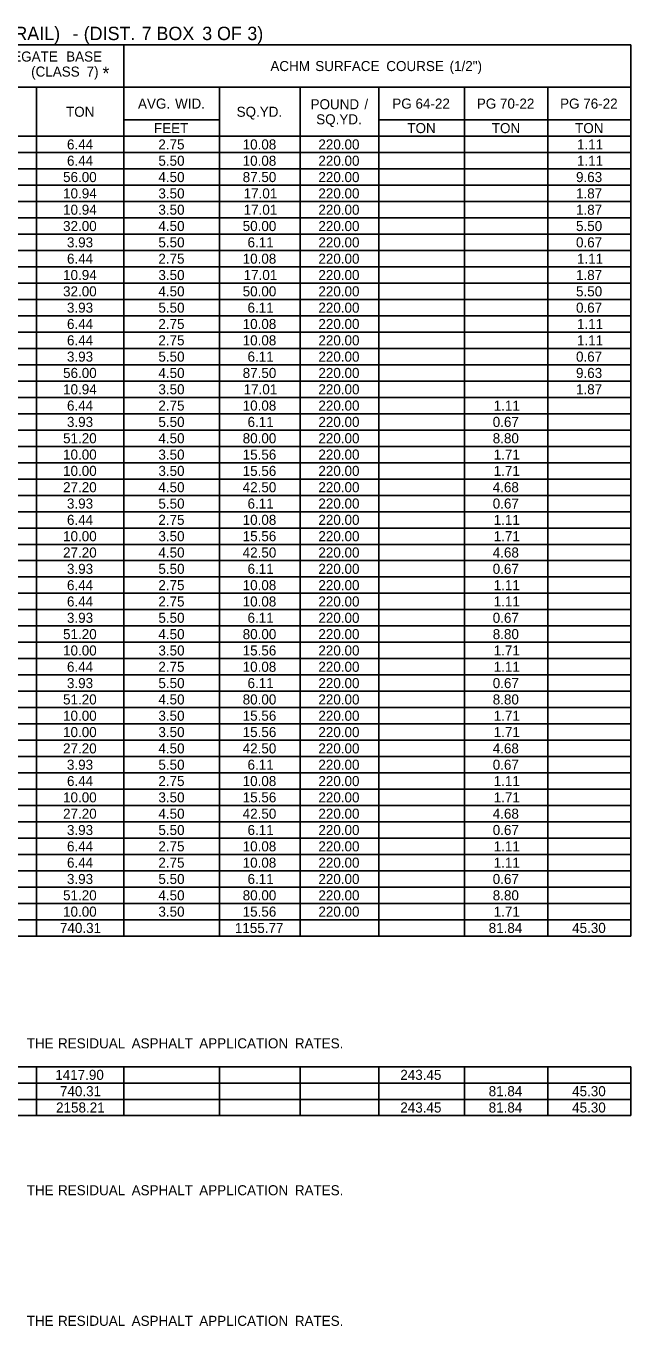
# Model space of a CAD drawing. Extents: x 544478 to 1930787, y -1948294 to 596640.
# Drawn here: x 554523 to 554884, y -1946915 to -1946138 of the extents above; entities that cross this region are included whole.
import ezdxf

# ---------------------------------------------------------------- set-up
doc = ezdxf.new("R2010")
doc.units = 0
doc.layers.add('Default', color=7, linetype='Continuous')

msp = doc.modelspace()

# ---------------------------------------------------------------- linework, layer by layer
at = {"layer": 'Default'}
for p, q in [((554061.9, -1946149.42), (554884.32, -1946149.42)), ((554581.58, -1946681.77), (554581.58, -1946149.42)), ((554884.32, -1946681.77), (554884.32, -1946149.42)), ((554479.69, -1946174.77), (554884.32, -1946174.77)), ((554529.42, -1946681.77), (554529.42, -1946174.77)), ((554638.62, -1946174.77), (554686.88, -1946174.77)), ((554638.62, -1946681.77), (554638.62, -1946174.77)), ((554686.88, -1946681.77), (554686.88, -1946174.77)), ((554733.68, -1946681.77), (554733.68, -1946174.77)), ((554784.87, -1946681.77), (554784.87, -1946174.77)), ((554834.59, -1946681.77), (554834.59, -1946174.77)), ((554581.58, -1946194.27), (554638.62, -1946194.27)), ((554581.58, -1946204.02), (554581.58, -1946194.27)), ((554638.62, -1946681.77), (554638.62, -1946194.27)), ((554733.68, -1946194.27), (554884.32, -1946194.27)), ((554061.9, -1946204.02), (554884.32, -1946204.02)), ((554479.69, -1946204.02), (554638.62, -1946204.02)), ((554529.42, -1946681.77), (554529.42, -1946204.02)), ((554638.62, -1946204.02), (554884.32, -1946204.02)), ((554686.88, -1946681.77), (554686.88, -1946204.02)), ((554307.6, -1946213.77), (554884.32, -1946213.77)), ((554307.6, -1946223.52), (554884.32, -1946223.52)), ((554307.6, -1946233.27), (554884.32, -1946233.27)), ((554307.6, -1946243.02), (554884.32, -1946243.02)), ((554307.6, -1946252.77), (554884.32, -1946252.77)), ((554307.6, -1946262.52), (554884.32, -1946262.52)), ((554307.6, -1946272.27), (554884.32, -1946272.27)), ((554307.6, -1946282.02), (554884.32, -1946282.02)), ((554307.6, -1946291.77), (554884.32, -1946291.77)), ((554307.6, -1946301.52), (554884.32, -1946301.52)), ((554307.6, -1946311.27), (554884.32, -1946311.27)), ((554307.6, -1946321.02), (554581.58, -1946321.02)), ((554529.42, -1946321.02), (554581.58, -1946321.02)), ((554581.58, -1946321.02), (554884.32, -1946321.02)), ((554307.6, -1946330.77), (554884.32, -1946330.77)), ((554307.6, -1946340.52), (554581.58, -1946340.52)), ((554529.42, -1946340.52), (554581.58, -1946340.52)), ((554581.58, -1946340.52), (554884.32, -1946340.52)), ((554307.6, -1946350.27), (554581.58, -1946350.27)), ((554529.42, -1946350.27), (554581.58, -1946350.27)), ((554581.58, -1946350.27), (554884.32, -1946350.27)), ((554061.9, -1946360.02), (554884.32, -1946360.02)), ((554307.6, -1946369.77), (554884.32, -1946369.77)), ((554307.6, -1946379.52), (554884.32, -1946379.52)), ((554307.6, -1946389.27), (554884.32, -1946389.27)), ((554307.6, -1946399.02), (554884.32, -1946399.02)), ((554307.6, -1946408.77), (554884.32, -1946408.77)), ((554307.6, -1946418.52), (554884.32, -1946418.52)), ((554307.6, -1946428.27), (554884.32, -1946428.27)), ((554307.6, -1946438.02), (554884.32, -1946438.02)), ((554307.6, -1946447.77), (554884.32, -1946447.77)), ((554307.6, -1946457.52), (554884.32, -1946457.52)), ((554307.6, -1946467.27), (554884.32, -1946467.27)), ((554307.6, -1946477.02), (554581.58, -1946477.02)), ((554529.42, -1946477.02), (554581.58, -1946477.02)), ((554581.58, -1946477.02), (554884.32, -1946477.02)), ((554307.6, -1946486.77), (554884.32, -1946486.77)), ((554307.6, -1946496.52), (554581.58, -1946496.52)), ((554529.42, -1946496.52), (554581.58, -1946496.52)), ((554581.58, -1946496.52), (554884.32, -1946496.52)), ((554307.6, -1946506.27), (554581.58, -1946506.27)), ((554529.42, -1946506.27), (554581.58, -1946506.27)), ((554581.58, -1946506.27), (554884.32, -1946506.27)), ((554061.9, -1946516.02), (554884.32, -1946516.02)), ((554307.6, -1946525.77), (554884.32, -1946525.77)), ((554307.6, -1946535.52), (554884.32, -1946535.52)), ((554307.6, -1946545.27), (554884.32, -1946545.27)), ((554307.6, -1946555.02), (554884.32, -1946555.02)), ((554307.6, -1946564.77), (554884.32, -1946564.77)), ((554307.6, -1946574.52), (554884.32, -1946574.52)), ((554307.6, -1946584.27), (554884.32, -1946584.27)), ((554307.6, -1946594.02), (554884.32, -1946594.02)), ((554307.6, -1946603.77), (554884.32, -1946603.77)), ((554307.6, -1946613.52), (554884.32, -1946613.52)), ((554307.6, -1946623.27), (554884.32, -1946623.27)), ((554307.6, -1946633.02), (554581.58, -1946633.02)), ((554529.42, -1946633.02), (554581.58, -1946633.02)), ((554581.58, -1946633.02), (554884.32, -1946633.02)), ((554307.6, -1946642.77), (554884.32, -1946642.77)), ((554307.6, -1946652.52), (554581.58, -1946652.52)), ((554529.42, -1946652.52), (554581.58, -1946652.52)), ((554581.58, -1946652.52), (554884.32, -1946652.52)), ((554307.6, -1946662.27), (554581.58, -1946662.27)), ((554529.42, -1946662.27), (554581.58, -1946662.27)), ((554581.58, -1946662.27), (554884.32, -1946662.27)), ((554061.9, -1946672.02), (554884.32, -1946672.02)), ((554733.68, -1946681.77), (554733.68, -1946672.02)), ((554307.6, -1946681.77), (554884.32, -1946681.77)), ((554244.23, -1946759.77), (554834.59, -1946759.77)), ((554244.23, -1946759.77), (554884.32, -1946759.77)), ((554529.42, -1946789.02), (554529.42, -1946759.77)), ((554581.58, -1946789.02), (554581.58, -1946759.77)), ((554638.62, -1946789.02), (554638.62, -1946759.77)), ((554686.88, -1946789.02), (554686.88, -1946759.77)), ((554733.68, -1946789.02), (554733.68, -1946759.77)), ((554784.87, -1946789.02), (554784.87, -1946759.77)), ((554834.59, -1946789.02), (554834.59, -1946759.77)), ((554884.32, -1946789.02), (554884.32, -1946759.77)), ((554244.23, -1946769.52), (554884.32, -1946769.52)), ((554244.23, -1946779.27), (554884.32, -1946779.27)), ((554581.58, -1946789.02), (554581.58, -1946779.27)), ((554638.62, -1946789.02), (554638.62, -1946779.27)), ((554686.88, -1946789.02), (554686.88, -1946779.27)), ((554733.68, -1946789.02), (554733.68, -1946779.27)), ((554244.23, -1946789.02), (554884.32, -1946789.02))]:
    msp.add_line(p, q, dxfattribs=at)

# ---------------------------------------------------------------- texts
for s, height, p in [(' GUARDRAIL)', 8, (554474.5, -1946146.6)), (' -', 8, (554547.81, -1946146.6)), (' (DIST.', 8, (554554.55, -1946146.6)), (' 7', 8, (554589.17, -1946146.6)), (' BOX', 8, (554598, -1946146.6)), (' 3', 8, (554625.31, -1946146.6)), (' OF', 8, (554634.15, -1946146.6)), (' 3)', 8, (554652.26, -1946146.6)), ('AGGREGATE', 6, (554491.22, -1946159.4)), (' BASE', 6, (554544.84, -1946159.4)), ('ACHM', 6, (554669.01, -1946165.1)), (' SURFACE', 6, (554693.56, -1946165.1)), (' COURSE', 6, (554736, -1946165.1)), (' (1/2")', 6, (554773.78, -1946165.1)), (' (CLASS', 6, (554523.91, -1946168.4)), (' 7)', 6, (554557.03, -1946168.4)), ('*', 8, (554568.7, -1946170.4)), ('AVG.', 6, (554589.95, -1946187.52)), (' WID.', 6, (554609.87, -1946187.52)), ('POUND', 6, (554693.01, -1946187.9)), (' /', 6, (554722.88, -1946187.9)), ('PG', 6, (554741.8, -1946187.52)), (' 64-22', 6, (554753.41, -1946187.52)), ('PG', 6, (554792.26, -1946187.52)), (' 70-22', 6, (554803.86, -1946187.52)), ('PG', 6, (554841.98, -1946187.52)), (' 76-22', 6, (554853.59, -1946187.52)), ('TON', 6, (554546.98, -1946192.4)), ('SQ.YD.', 6, (554648.83, -1946192.4)), ('SQ.YD.', 6, (554696.36, -1946196.9)), ('FEET', 6, (554599.47, -1946202.15)), ('TON', 6, (554750.76, -1946202.15)), ('TON', 6, (554801.21, -1946202.15)), ('TON', 6, (554850.94, -1946202.15)), ('6.44', 6, (554547.55, -1946211.9)), ('2.75', 6, (554602.11, -1946211.9)), ('10.08', 6, (554652.45, -1946211.9)), ('220.00', 6, (554697.66, -1946211.9)), ('1.11', 6, (554852.07, -1946211.9)), ('6.44', 6, (554547.55, -1946221.65)), ('5.50', 6, (554602.14, -1946221.65)), ('10.08', 6, (554652.45, -1946221.65)), ('220.00', 6, (554697.66, -1946221.65)), ('1.11', 6, (554852.07, -1946221.65)), ('56.00', 6, (554545.21, -1946231.4)), ('4.50', 6, (554602.14, -1946231.4)), ('87.50', 6, (554652.46, -1946231.4)), ('220.00', 6, (554697.66, -1946231.4)), ('9.63', 6, (554851.49, -1946231.4)), ('10.94', 6, (554545.22, -1946241.15)), ('3.50', 6, (554602.14, -1946241.15)), ('17.01', 6, (554653.03, -1946241.15)), ('220.00', 6, (554697.66, -1946241.15)), ('1.87', 6, (554851.49, -1946241.15)), ('10.94', 6, (554545.22, -1946250.9)), ('3.50', 6, (554602.14, -1946250.9)), ('17.01', 6, (554653.03, -1946250.9)), ('220.00', 6, (554697.66, -1946250.9)), ('1.87', 6, (554851.49, -1946250.9)), ('32.00', 6, (554545.21, -1946260.65)), ('4.50', 6, (554602.14, -1946260.65)), ('50.00', 6, (554652.46, -1946260.65)), ('220.00', 6, (554697.66, -1946260.65)), ('5.50', 6, (554851.5, -1946260.65)), ('3.93', 6, (554547.53, -1946270.4)), ('5.50', 6, (554602.14, -1946270.4)), ('6.11', 6, (554655.36, -1946270.4)), ('220.00', 6, (554697.66, -1946270.4)), ('0.67', 6, (554851.49, -1946270.4)), ('6.44', 6, (554547.55, -1946280.15)), ('2.75', 6, (554602.11, -1946280.15)), ('10.08', 6, (554652.45, -1946280.15)), ('220.00', 6, (554697.66, -1946280.15)), ('1.11', 6, (554852.07, -1946280.15)), ('10.94', 6, (554545.22, -1946289.9)), ('3.50', 6, (554602.14, -1946289.9)), ('17.01', 6, (554653.03, -1946289.9)), ('220.00', 6, (554697.66, -1946289.9)), ('1.87', 6, (554851.49, -1946289.9)), ('32.00', 6, (554545.21, -1946299.65)), ('4.50', 6, (554602.14, -1946299.65)), ('50.00', 6, (554652.46, -1946299.65)), ('220.00', 6, (554697.66, -1946299.65)), ('5.50', 6, (554851.5, -1946299.65)), ('3.93', 6, (554547.53, -1946309.4)), ('5.50', 6, (554602.14, -1946309.4)), ('6.11', 6, (554655.36, -1946309.4)), ('220.00', 6, (554697.66, -1946309.4)), ('0.67', 6, (554851.49, -1946309.4)), ('6.44', 6, (554547.55, -1946319.15)), ('2.75', 6, (554602.11, -1946319.15)), ('10.08', 6, (554652.45, -1946319.15)), ('220.00', 6, (554697.66, -1946319.15)), ('1.11', 6, (554852.07, -1946319.15)), ('6.44', 6, (554547.55, -1946328.9)), ('2.75', 6, (554602.11, -1946328.9)), ('10.08', 6, (554652.45, -1946328.9)), ('220.00', 6, (554697.66, -1946328.9)), ('1.11', 6, (554852.07, -1946328.9)), ('3.93', 6, (554547.53, -1946338.65)), ('5.50', 6, (554602.14, -1946338.65)), ('6.11', 6, (554655.36, -1946338.65)), ('220.00', 6, (554697.66, -1946338.65)), ('0.67', 6, (554851.49, -1946338.65)), ('56.00', 6, (554545.21, -1946348.4)), ('4.50', 6, (554602.14, -1946348.4)), ('87.50', 6, (554652.46, -1946348.4)), ('220.00', 6, (554697.66, -1946348.4)), ('9.63', 6, (554851.49, -1946348.4)), ('10.94', 6, (554545.22, -1946358.15)), ('3.50', 6, (554602.14, -1946358.15)), ('17.01', 6, (554653.03, -1946358.15)), ('220.00', 6, (554697.66, -1946358.15)), ('1.87', 6, (554851.49, -1946358.15)), ('6.44', 6, (554547.55, -1946367.9)), ('2.75', 6, (554602.11, -1946367.9)), ('10.08', 6, (554652.45, -1946367.9)), ('220.00', 6, (554697.66, -1946367.9)), ('1.11', 6, (554802.34, -1946367.9)), ('3.93', 6, (554547.53, -1946377.65)), ('5.50', 6, (554602.14, -1946377.65)), ('6.11', 6, (554655.36, -1946377.65)), ('220.00', 6, (554697.66, -1946377.65)), ('0.67', 6, (554801.76, -1946377.65)), ('51.20', 6, (554545.21, -1946387.4)), ('4.50', 6, (554602.14, -1946387.4)), ('80.00', 6, (554652.46, -1946387.4)), ('220.00', 6, (554697.66, -1946387.4)), ('8.80', 6, (554801.77, -1946387.4)), ('10.00', 6, (554545.21, -1946397.15)), ('3.50', 6, (554602.14, -1946397.15)), ('15.56', 6, (554652.45, -1946397.15)), ('220.00', 6, (554697.66, -1946397.15)), ('1.71', 6, (554802.34, -1946397.15)), ('10.00', 6, (554545.21, -1946406.9)), ('3.50', 6, (554602.14, -1946406.9)), ('15.56', 6, (554652.45, -1946406.9)), ('220.00', 6, (554697.66, -1946406.9)), ('1.71', 6, (554802.34, -1946406.9)), ('27.20', 6, (554545.21, -1946416.65)), ('4.50', 6, (554602.14, -1946416.65)), ('42.50', 6, (554652.46, -1946416.65)), ('220.00', 6, (554697.66, -1946416.65)), ('4.68', 6, (554801.76, -1946416.65)), ('3.93', 6, (554547.53, -1946426.4)), ('5.50', 6, (554602.14, -1946426.4)), ('6.11', 6, (554655.36, -1946426.4)), ('220.00', 6, (554697.66, -1946426.4)), ('0.67', 6, (554801.76, -1946426.4)), ('6.44', 6, (554547.55, -1946436.15)), ('2.75', 6, (554602.11, -1946436.15)), ('10.08', 6, (554652.45, -1946436.15)), ('220.00', 6, (554697.66, -1946436.15)), ('1.11', 6, (554802.34, -1946436.15)), ('10.00', 6, (554545.21, -1946445.9)), ('3.50', 6, (554602.14, -1946445.9)), ('15.56', 6, (554652.45, -1946445.9)), ('220.00', 6, (554697.66, -1946445.9)), ('1.71', 6, (554802.34, -1946445.9)), ('27.20', 6, (554545.21, -1946455.65)), ('4.50', 6, (554602.14, -1946455.65)), ('42.50', 6, (554652.46, -1946455.65)), ('220.00', 6, (554697.66, -1946455.65)), ('4.68', 6, (554801.76, -1946455.65)), ('3.93', 6, (554547.53, -1946465.4)), ('5.50', 6, (554602.14, -1946465.4)), ('6.11', 6, (554655.36, -1946465.4)), ('220.00', 6, (554697.66, -1946465.4)), ('0.67', 6, (554801.76, -1946465.4)), ('6.44', 6, (554547.55, -1946475.15)), ('2.75', 6, (554602.11, -1946475.15)), ('10.08', 6, (554652.45, -1946475.15)), ('220.00', 6, (554697.66, -1946475.15)), ('1.11', 6, (554802.34, -1946475.15)), ('6.44', 6, (554547.55, -1946484.9)), ('2.75', 6, (554602.11, -1946484.9)), ('10.08', 6, (554652.45, -1946484.9)), ('220.00', 6, (554697.66, -1946484.9)), ('1.11', 6, (554802.34, -1946484.9)), ('3.93', 6, (554547.53, -1946494.65)), ('5.50', 6, (554602.14, -1946494.65)), ('6.11', 6, (554655.36, -1946494.65)), ('220.00', 6, (554697.66, -1946494.65)), ('0.67', 6, (554801.76, -1946494.65)), ('51.20', 6, (554545.21, -1946504.4)), ('4.50', 6, (554602.14, -1946504.4)), ('80.00', 6, (554652.46, -1946504.4)), ('220.00', 6, (554697.66, -1946504.4)), ('8.80', 6, (554801.77, -1946504.4)), ('10.00', 6, (554545.21, -1946514.15)), ('3.50', 6, (554602.14, -1946514.15)), ('15.56', 6, (554652.45, -1946514.15)), ('220.00', 6, (554697.66, -1946514.15)), ('1.71', 6, (554802.34, -1946514.15)), ('6.44', 6, (554547.55, -1946523.9)), ('2.75', 6, (554602.11, -1946523.9)), ('10.08', 6, (554652.45, -1946523.9)), ('220.00', 6, (554697.66, -1946523.9)), ('1.11', 6, (554802.34, -1946523.9)), ('3.93', 6, (554547.53, -1946533.65)), ('5.50', 6, (554602.14, -1946533.65)), ('6.11', 6, (554655.36, -1946533.65)), ('220.00', 6, (554697.66, -1946533.65)), ('0.67', 6, (554801.76, -1946533.65)), ('51.20', 6, (554545.21, -1946543.4)), ('4.50', 6, (554602.14, -1946543.4)), ('80.00', 6, (554652.46, -1946543.4)), ('220.00', 6, (554697.66, -1946543.4)), ('8.80', 6, (554801.77, -1946543.4)), ('10.00', 6, (554545.21, -1946553.15)), ('3.50', 6, (554602.14, -1946553.15)), ('15.56', 6, (554652.45, -1946553.15)), ('220.00', 6, (554697.66, -1946553.15)), ('1.71', 6, (554802.34, -1946553.15)), ('10.00', 6, (554545.21, -1946562.9)), ('3.50', 6, (554602.14, -1946562.9)), ('15.56', 6, (554652.45, -1946562.9)), ('220.00', 6, (554697.66, -1946562.9)), ('1.71', 6, (554802.34, -1946562.9)), ('27.20', 6, (554545.21, -1946572.65)), ('4.50', 6, (554602.14, -1946572.65)), ('42.50', 6, (554652.46, -1946572.65)), ('220.00', 6, (554697.66, -1946572.65)), ('4.68', 6, (554801.76, -1946572.65)), ('3.93', 6, (554547.53, -1946582.4)), ('5.50', 6, (554602.14, -1946582.4)), ('6.11', 6, (554655.36, -1946582.4)), ('220.00', 6, (554697.66, -1946582.4)), ('0.67', 6, (554801.76, -1946582.4)), ('6.44', 6, (554547.55, -1946592.15)), ('2.75', 6, (554602.11, -1946592.15)), ('10.08', 6, (554652.45, -1946592.15)), ('220.00', 6, (554697.66, -1946592.15)), ('1.11', 6, (554802.34, -1946592.15)), ('10.00', 6, (554545.21, -1946601.9)), ('3.50', 6, (554602.14, -1946601.9)), ('15.56', 6, (554652.45, -1946601.9)), ('220.00', 6, (554697.66, -1946601.9)), ('1.71', 6, (554802.34, -1946601.9)), ('27.20', 6, (554545.21, -1946611.65)), ('4.50', 6, (554602.14, -1946611.65)), ('42.50', 6, (554652.46, -1946611.65)), ('220.00', 6, (554697.66, -1946611.65)), ('4.68', 6, (554801.76, -1946611.65)), ('3.93', 6, (554547.53, -1946621.4)), ('5.50', 6, (554602.14, -1946621.4)), ('6.11', 6, (554655.36, -1946621.4)), ('220.00', 6, (554697.66, -1946621.4)), ('0.67', 6, (554801.76, -1946621.4)), ('6.44', 6, (554547.55, -1946631.15)), ('2.75', 6, (554602.11, -1946631.15)), ('10.08', 6, (554652.45, -1946631.15)), ('220.00', 6, (554697.66, -1946631.15)), ('1.11', 6, (554802.34, -1946631.15)), ('6.44', 6, (554547.55, -1946640.9)), ('2.75', 6, (554602.11, -1946640.9)), ('10.08', 6, (554652.45, -1946640.9)), ('220.00', 6, (554697.66, -1946640.9)), ('1.11', 6, (554802.34, -1946640.9)), ('3.93', 6, (554547.53, -1946650.65)), ('5.50', 6, (554602.14, -1946650.65)), ('6.11', 6, (554655.36, -1946650.65)), ('220.00', 6, (554697.66, -1946650.65)), ('0.67', 6, (554801.76, -1946650.65)), ('51.20', 6, (554545.21, -1946660.4)), ('4.50', 6, (554602.14, -1946660.4)), ('80.00', 6, (554652.46, -1946660.4)), ('220.00', 6, (554697.66, -1946660.4)), ('8.80', 6, (554801.77, -1946660.4)), ('10.00', 6, (554545.21, -1946670.15)), ('3.50', 6, (554602.14, -1946670.15)), ('15.56', 6, (554652.45, -1946670.15)), ('220.00', 6, (554697.66, -1946670.15)), ('1.71', 6, (554802.34, -1946670.15)), ('740.31', 6, (554543.36, -1946679.9)), ('1155.77', 6, (554647.79, -1946679.9)), ('81.84', 6, (554799.34, -1946679.9)), ('45.30', 6, (554849.17, -1946679.9)), (' THE', 6, (554521.32, -1946748.82)), (' RESIDUAL', 6, (554539.97, -1946748.82)), (' ASPHALT', 6, (554583.93, -1946748.82)), (' APPLICATION', 6, (554624.3, -1946748.82)), (' RATES.', 6, (554681.38, -1946748.82)), ('1417.90', 6, (554540.56, -1946767.65)), ('243.45', 6, (554746.58, -1946767.65)), ('740.31', 6, (554543.36, -1946777.4)), ('81.84', 6, (554799.34, -1946777.4)), ('45.30', 6, (554849.17, -1946777.4)), ('2158.21', 6, (554541.03, -1946787.15)), ('243.45', 6, (554746.58, -1946787.15)), ('81.84', 6, (554799.34, -1946787.15)), ('45.30', 6, (554849.17, -1946787.15)), (' THE', 6, (554521.32, -1946836.57)), (' RESIDUAL', 6, (554539.97, -1946836.57)), (' ASPHALT', 6, (554583.93, -1946836.57)), (' APPLICATION', 6, (554624.3, -1946836.57)), (' RATES.', 6, (554681.38, -1946836.57)), (' THE', 6, (554521.32, -1946914.57)), (' RESIDUAL', 6, (554539.97, -1946914.57)), (' ASPHALT', 6, (554583.93, -1946914.57)), (' APPLICATION', 6, (554624.3, -1946914.57)), (' RATES.', 6, (554681.38, -1946914.57))]:
    msp.add_text(s, height=height, dxfattribs=at).set_placement(p)

doc.saveas('drawing.dxf')
